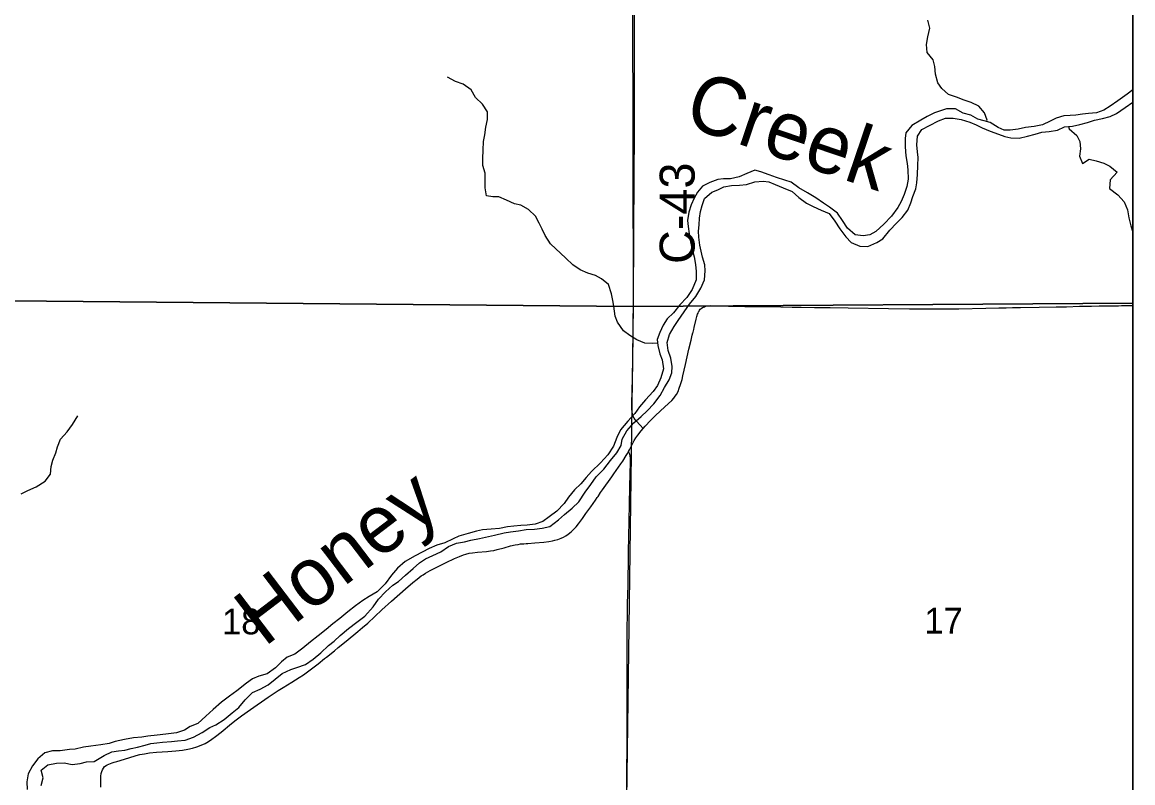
# Model space of a CAD drawing. Extents: x 0 to 34, y 0 to 22.
# Drawn here: x 8.498 to 9.4, y 16.023 to 16.64 of the extents above; entities that cross this region are included whole.
import ezdxf

# ---------------------------------------------------------------- set-up
doc = ezdxf.new("R2010")
doc.units = 0
for name, color, linetype in [('GM_X_County', 7, 'Continuous'), ('GM_X_County_Road', 7, 'Continuous'), ('GM_X_County_Road_Text', 7, 'Continuous'), ('GM_X_Major_River', 7, 'Continuous'), ('GM_X_Major_River_Text', 7, 'Continuous'), ('GM_X_Minor_River', 7, 'Continuous'), ('GM_X_Section', 7, 'Continuous'), ('GM_X_Section_Text', 7, 'Continuous'), ('GM_X_Township', 7, 'Continuous'), ('SH_Data', 7, 'Continuous')]:
    doc.layers.add(name, color=color, linetype=linetype)

msp = doc.modelspace()

# ---------------------------------------------------------------- linework, layer by layer
at = {"layer": 'GM_X_County'}
msp.add_lwpolyline([(9.4, 14.3965), (9.4, 20.9), (2.6, 20.9), (2.6, 14.40919)], dxfattribs=at)
at = {"layer": 'GM_X_County_Road'}
for points in [[(8.99502, 16.63515), (8.99502, 16.64036), (8.99492, 16.65621), (8.99479, 16.66709), (8.99461, 16.68542), (8.99452, 16.69817), (8.99432, 16.71308), (8.9942, 16.72272), (8.99394, 16.73732), (8.99376, 16.75037), (8.9935, 16.77367), (8.99338, 16.78765), (8.99286, 16.83177), (8.99286, 16.85104), (8.99279, 16.86284), (8.99299, 16.89795), (8.99316, 16.91502)], [(8.9947, 16.47621), (8.9947, 16.47732), (8.99482, 16.50653), (8.99498, 16.52734), (8.99508, 16.5376), (8.99515, 16.54752), (8.99518, 16.55526), (8.99515, 16.56581), (8.99511, 16.57793), (8.99505, 16.58942), (8.99506, 16.59377), (8.99506, 16.60153), (8.99504, 16.61488), (8.99502, 16.63515)], [(9.00208, 16.31029), (8.99966, 16.3131), (8.99951, 16.31327), (8.9968, 16.3162), (8.99611, 16.31695), (8.99542, 16.31779), (8.9949, 16.3186), (8.99448, 16.31932), (8.99417, 16.31997), (8.99392, 16.3207), (8.99352, 16.32214), (8.99337, 16.32311), (8.99322, 16.32429), (8.99311, 16.3255), (8.99302, 16.32701), (8.993, 16.3304), (8.99346, 16.35121), (8.99372, 16.36146), (8.99393, 16.37358), (8.99401, 16.37886), (8.99409, 16.38477), (8.99416, 16.39532), (8.99434, 16.4124), (8.99441, 16.42079), (8.99447, 16.42731), (8.99447, 16.43259), (8.99462, 16.44966), (8.9947, 16.47621)], [(9.00208, 16.31029), (9.00377, 16.31219), (9.00827, 16.31691), (9.01204, 16.32061), (9.01636, 16.32464), (9.02279, 16.33051), (9.02542, 16.33314), (9.02706, 16.33502), (9.02826, 16.33661), (9.02921, 16.33804), (9.03052, 16.3405), (9.03156, 16.3431), (9.03256, 16.34604), (9.03376, 16.35022), (9.03452, 16.35323), (9.03665, 16.36231), (9.03942, 16.37475), (9.04111, 16.38201), (9.04212, 16.38624), (9.04256, 16.38805), (9.04275, 16.38864), (9.04326, 16.39076), (9.04367, 16.39226), (9.04532, 16.39921), (9.04587, 16.40132), (9.04642, 16.4031), (9.04682, 16.4041), (9.04722, 16.40495), (9.04758, 16.40565), (9.04807, 16.40648), (9.04863, 16.40716), (9.04938, 16.4079), (9.05029, 16.40852), (9.0511, 16.40892), (9.05194, 16.40927), (9.05284, 16.40957), (9.05465, 16.4099), (9.05682, 16.41009), (9.05934, 16.41006), (9.06276, 16.40996), (9.06525, 16.40996), (9.06773, 16.40987), (9.07146, 16.40977), (9.07643, 16.40968), (9.08482, 16.40947), (9.09507, 16.40936), (9.11403, 16.4091), (9.12335, 16.40898), (9.12584, 16.40894), (9.1305, 16.4089), (9.14137, 16.40873), (9.15411, 16.40854), (9.16872, 16.40837), (9.20164, 16.40788), (9.21871, 16.4076), (9.22679, 16.40754), (9.24046, 16.40741), (9.24916, 16.40743), (9.25879, 16.40758), (9.28054, 16.40811), (9.2911, 16.4083), (9.297, 16.40844), (9.30229, 16.40848), (9.30881, 16.40856), (9.32403, 16.40875), (9.3377, 16.40901), (9.34608, 16.40925), (9.35664, 16.40959), (9.36658, 16.40977), (9.37279, 16.40986), (9.37775, 16.40987), (9.38302, 16.40994), (9.38457, 16.40996), (9.38829, 16.41003), (9.39078, 16.41009), (9.39325, 16.41015), (9.4, 16.41027)], [(8.99035, 16.29169), (8.99096, 16.29288), (8.9937, 16.29844), (8.9949, 16.30062), (8.99621, 16.30274), (8.99779, 16.30504), (9.00046, 16.30847), (9.00208, 16.31029)], [(8.56163, 16.0191), (8.56151, 16.02532), (8.56159, 16.02813), (8.56187, 16.03029), (8.56224, 16.03179), (8.56281, 16.03323), (8.5636, 16.03458), (8.5646, 16.03574), (8.56582, 16.03668), (8.56677, 16.03724), (8.56806, 16.03779), (8.56944, 16.03838), (8.57065, 16.03875), (8.57241, 16.03934), (8.57466, 16.03997), (8.57718, 16.04074), (8.58164, 16.04207), (8.58432, 16.04287), (8.59027, 16.04468), (8.59327, 16.04549), (8.59691, 16.04627), (8.60121, 16.04692), (8.60678, 16.0474), (8.61609, 16.04797), (8.62259, 16.04854), (8.62784, 16.04919), (8.63213, 16.04989), (8.63607, 16.05077), (8.63966, 16.05181), (8.64315, 16.05311), (8.64623, 16.05457), (8.64894, 16.0561), (8.65181, 16.05794), (8.65484, 16.06012), (8.65946, 16.0638), (8.66781, 16.07078), (8.67146, 16.07367), (8.67594, 16.07703), (8.68327, 16.08227), (8.69756, 16.09221), (8.70563, 16.09747), (8.70957, 16.09996), (8.71674, 16.1043), (8.72276, 16.10816), (8.72611, 16.11042), (8.73166, 16.11441), (8.73808, 16.1193), (8.74342, 16.12351), (8.74486, 16.12467), (8.7514, 16.12992), (8.75451, 16.13249), (8.76077, 16.13761), (8.77044, 16.14542), (8.77423, 16.14863), (8.7784, 16.15236), (8.79, 16.16314), (8.79761, 16.17002), (8.80903, 16.1801), (8.81514, 16.18538), (8.81856, 16.18808), (8.82015, 16.18926), (8.82191, 16.19057), (8.82345, 16.19159), (8.82538, 16.19284), (8.82737, 16.19398), (8.82924, 16.195), (8.83336, 16.19718), (8.84227, 16.20161), (8.84902, 16.20478), (8.85302, 16.20649), (8.85621, 16.20771), (8.85804, 16.20835), (8.86082, 16.20904), (8.86345, 16.20945), (8.86746, 16.20991), (8.8749, 16.21051), (8.87829, 16.21095), (8.88074, 16.21137), (8.88346, 16.21198), (8.88917, 16.21354), (8.89428, 16.21495), (8.89816, 16.21585), (8.90053, 16.21627), (8.90262, 16.21655), (8.90337, 16.21658), (8.90382, 16.21668), (8.90447, 16.21671), (8.90532, 16.21681), (8.90703, 16.21694), (8.90841, 16.21704), (8.91413, 16.21749), (8.92155, 16.21815), (8.92556, 16.21865), (8.92862, 16.21919), (8.93043, 16.21961), (8.93282, 16.22028), (8.93546, 16.22122), (8.93743, 16.22213), (8.93932, 16.22321), (8.94139, 16.22458), (8.9436, 16.2263), (8.94566, 16.22819), (8.94779, 16.23045), (8.94975, 16.23286), (8.95303, 16.23738), (8.95571, 16.24119), (8.95958, 16.24682), (8.96335, 16.25215), (8.96477, 16.25418), (8.9655, 16.25519), (8.96753, 16.25828), (8.96917, 16.26054), (8.97673, 16.27118), (8.97836, 16.27345), (8.98408, 16.28159), (8.98563, 16.28391), (8.98849, 16.28833), (8.98956, 16.29016), (8.99035, 16.29169)], [(8.98879, 16.01776), (8.98889, 16.03267), (8.98912, 16.05132), (8.9892, 16.06842), (8.98925, 16.0852), (8.98932, 16.09949), (8.98931, 16.10882), (8.98926, 16.11814), (8.98922, 16.12436), (8.9892, 16.13368), (8.98918, 16.13803), (8.9892, 16.14237), (8.98924, 16.14641), (8.98929, 16.15076), (8.98939, 16.15666), (8.98944, 16.16162), (8.98957, 16.16659), (8.9896, 16.16814), (8.98994, 16.18274), (8.99002, 16.1874), (8.99012, 16.19206), (8.99024, 16.1989), (8.99041, 16.21351), (8.99051, 16.21941), (8.99057, 16.22406), (8.99081, 16.23369), (8.99109, 16.25047), (8.9913, 16.26103), (8.99135, 16.2629), (8.9916, 16.27346), (8.99178, 16.28278), (8.99182, 16.28589), (8.99182, 16.28662), (8.99172, 16.28757), (8.99163, 16.28843), (8.99146, 16.28925), (8.99116, 16.29007), (8.99035, 16.29169)]]:
    msp.add_lwpolyline(points, dxfattribs=at)
at = {"layer": 'GM_X_Major_River'}
for points in [[(9.4, 16.58542), (9.39539, 16.58195), (9.38796, 16.57629), (9.38149, 16.57196), (9.37654, 16.56875), (9.37046, 16.56669), (9.36401, 16.56615), (9.35926, 16.5656), (9.35375, 16.56486), (9.34901, 16.5645)], [(9.34901, 16.5645), (9.34388, 16.56415), (9.3378, 16.56247), (9.33285, 16.55983), (9.32658, 16.55701), (9.31974, 16.55571), (9.31271, 16.55479), (9.30682, 16.55349), (9.30037, 16.55257), (9.29543, 16.55259), (9.29051, 16.55489), (9.28407, 16.5589), (9.27933, 16.56006), (9.27403, 16.5616), (9.26854, 16.56485), (9.26209, 16.56639), (9.25603, 16.56983), (9.24863, 16.56986), (9.24388, 16.56837), (9.23894, 16.56668), (9.23285, 16.56367), (9.2279, 16.56085), (9.22048, 16.55632), (9.21552, 16.55046), (9.21512, 16.54572), (9.21509, 16.53908), (9.21563, 16.53168), (9.21674, 16.52541), (9.21729, 16.52047), (9.21745, 16.51289), (9.21647, 16.50682), (9.21417, 16.50038), (9.21186, 16.49469), (9.20899, 16.48977), (9.20384, 16.48277), (9.19774, 16.47616), (9.19126, 16.4703), (9.18631, 16.46767), (9.181, 16.46674), (9.17436, 16.46753), (9.16831, 16.47306), (9.16416, 16.47934), (9.1602, 16.48524), (9.15358, 16.49001), (9.14866, 16.49344), (9.1426, 16.49765), (9.1356, 16.50166), (9.12859, 16.50586), (9.12235, 16.51044), (9.11723, 16.51198), (9.1106, 16.5141), (9.10453, 16.51621), (9.09771, 16.51871), (9.09297, 16.52025), (9.08632, 16.51743), (9.08023, 16.5148), (9.07302, 16.51312), (9.06751, 16.51296), (9.06276, 16.51241), (9.0563, 16.51016), (9.0504, 16.50715), (9.04621, 16.50223), (9.04353, 16.49731), (9.04123, 16.49201), (9.0393, 16.48594), (9.03833, 16.47931), (9.03887, 16.47437), (9.03961, 16.46829), (9.04034, 16.46336), (9.04184, 16.45671), (9.04351, 16.44987), (9.04463, 16.44361), (9.04517, 16.43772), (9.04514, 16.43108), (9.04207, 16.42312), (9.03768, 16.41669), (9.03196, 16.41083), (9.0268, 16.4044), (9.02166, 16.3993), (9.01841, 16.39438), (9.01573, 16.38832), (9.01361, 16.38264), (9.01416, 16.3777), (9.01565, 16.37087), (9.01753, 16.36612), (9.01864, 16.35871), (9.01652, 16.35151), (9.01383, 16.34526), (9.0104, 16.34034), (9.0041, 16.33354), (8.99915, 16.32786), (8.99533, 16.32257), (8.9898, 16.31633), (8.98388, 16.30914), (8.98082, 16.3029), (8.97813, 16.29589), (8.97336, 16.28908), (8.96744, 16.28246), (8.9602, 16.27547), (8.95601, 16.27055), (8.95143, 16.26545)], [(9.22549, 16.53031), (9.22513, 16.53505), (9.22459, 16.54075), (9.225, 16.54777), (9.22863, 16.55325), (9.23472, 16.55645), (9.24213, 16.56022), (9.24784, 16.56228), (9.2541, 16.56225), (9.26055, 16.56128), (9.26756, 16.55916), (9.27268, 16.55705), (9.2776, 16.55456), (9.28404, 16.55169), (9.29086, 16.54938), (9.29617, 16.54746), (9.30091, 16.5463), (9.30774, 16.54608), (9.31439, 16.54776), (9.32066, 16.54926), (9.32598, 16.55094), (9.33206, 16.55148), (9.3387, 16.55259), (9.34441, 16.55523), (9.35106, 16.55596), (9.35694, 16.55707), (9.36322, 16.55894), (9.36892, 16.56062), (9.37538, 16.56212), (9.38165, 16.5638), (9.38678, 16.56605), (9.39382, 16.57096), (9.4, 16.57537)], [(8.80914, 16.19111), (8.81543, 16.19658), (8.82038, 16.20131), (8.82533, 16.20451), (8.83142, 16.20733), (8.83769, 16.21015), (8.84398, 16.21449), (8.85063, 16.21712), (8.8569, 16.21823), (8.86222, 16.21972), (8.86925, 16.22102), (8.87646, 16.22251), (8.8814, 16.22363), (8.88919, 16.22549), (8.89451, 16.22641), (8.90078, 16.22734), (8.90705, 16.22845), (8.91388, 16.22861), (8.92015, 16.22934), (8.92623, 16.23083), (8.93346, 16.23612), (8.93823, 16.24046), (8.94451, 16.24574), (8.95004, 16.25085), (8.9552, 16.2586), (8.95978, 16.26485), (8.96398, 16.27109), (8.97027, 16.27732), (8.97561, 16.28432), (8.98076, 16.29056), (8.98421, 16.29662), (8.98518, 16.30155), (8.989, 16.30836), (8.99454, 16.31498), (9.00044, 16.32008), (9.00539, 16.32461), (9.01092, 16.33047), (9.01589, 16.33709), (9.01952, 16.34353), (9.02334, 16.34996), (9.02546, 16.35564), (9.02567, 16.36058), (9.02456, 16.36741), (9.0225, 16.37368), (9.02177, 16.38014), (9.02369, 16.38658), (9.02733, 16.39321), (9.03057, 16.39813), (9.03554, 16.40513), (9.03974, 16.41118), (9.04508, 16.41761), (9.0491, 16.42423), (9.05197, 16.43105), (9.05257, 16.43845), (9.0524, 16.44319), (9.05034, 16.44946), (9.04923, 16.45421), (9.04811, 16.45915), (9.04738, 16.46579), (9.04702, 16.47054), (9.04761, 16.47566), (9.04801, 16.48116), (9.0488, 16.48647), (9.05015, 16.4914), (9.05207, 16.49708), (9.05797, 16.50218), (9.06273, 16.50425), (9.06786, 16.5065), (9.07394, 16.5078), (9.08058, 16.50797), (9.08609, 16.50851), (9.09293, 16.51076), (9.09958, 16.51111), (9.10432, 16.51052), (9.10943, 16.50841), (9.11588, 16.50573), (9.12327, 16.50285), (9.12856, 16.49789), (9.1348, 16.49331), (9.14029, 16.49063), (9.14673, 16.48776), (9.15336, 16.48489), (9.15789, 16.4788), (9.16185, 16.47252), (9.16695, 16.46604), (9.17129, 16.46128), (9.17811, 16.45841), (9.18475, 16.458), (9.19198, 16.46138), (9.19693, 16.4644), (9.20265, 16.47139), (9.20799, 16.47706), (9.21276, 16.48179), (9.21734, 16.48765), (9.21964, 16.49371), (9.22118, 16.49864), (9.22368, 16.50508), (9.22464, 16.50982), (9.22505, 16.51665), (9.22546, 16.52386), (9.22549, 16.53031)], [(8.95143, 16.26545), (8.94647, 16.26054), (8.94151, 16.25449), (8.93807, 16.24938), (8.93197, 16.24314), (8.92569, 16.23862), (8.92055, 16.23484), (8.91447, 16.23259), (8.90782, 16.23186), (8.90289, 16.23169), (8.897, 16.23115), (8.89206, 16.23041), (8.8856, 16.22911), (8.87877, 16.22857), (8.87174, 16.22803), (8.86681, 16.2271), (8.85996, 16.22505), (8.85255, 16.2228), (8.8478, 16.22073), (8.84095, 16.21754), (8.83468, 16.21548), (8.82841, 16.21285), (8.8227, 16.20984), (8.81699, 16.20701), (8.80881, 16.20231), (8.80271, 16.19683), (8.79776, 16.19116), (8.7926, 16.18416), (8.78612, 16.17773), (8.77946, 16.17397), (8.77432, 16.17076), (8.76842, 16.16642), (8.76233, 16.16152), (8.75585, 16.15604), (8.74995, 16.1517), (8.74461, 16.14717), (8.73814, 16.14189), (8.73185, 16.13717), (8.72576, 16.13207), (8.71929, 16.12717), (8.71301, 16.12473), (8.70825, 16.12076), (8.70348, 16.11604), (8.69663, 16.11114), (8.68998, 16.10927), (8.68466, 16.10701), (8.6799, 16.10362), (8.67209, 16.0972), (8.666, 16.09305), (8.65952, 16.08815), (8.65285, 16.0821), (8.64676, 16.07663), (8.64028, 16.07077), (8.63419, 16.06833), (8.62944, 16.0655), (8.62297, 16.06326), (8.61443, 16.06215), (8.6074, 16.06123), (8.59981, 16.06051), (8.59487, 16.05977), (8.58803, 16.05923), (8.58082, 16.05774), (8.57322, 16.05626), (8.56846, 16.05457), (8.56144, 16.05346), (8.55346, 16.05236), (8.54757, 16.05144), (8.54073, 16.04995), (8.53599, 16.04959), (8.52858, 16.04867), (8.52232, 16.0487), (8.51605, 16.04702), (8.51033, 16.04211), (8.50594, 16.03644), (8.5025, 16.02981), (8.50152, 16.02336), (8.50169, 16.0171)], [(8.51309, 16.02047), (8.51463, 16.02653), (8.51295, 16.0328), (8.51847, 16.03714), (8.5255, 16.03863), (8.53177, 16.03879), (8.53821, 16.03743), (8.54486, 16.03835), (8.54999, 16.03966), (8.55625, 16.04001), (8.56425, 16.04491), (8.57052, 16.04773), (8.57603, 16.04847), (8.58116, 16.0492), (8.58629, 16.05051), (8.59142, 16.05163), (8.5975, 16.05331), (8.60225, 16.05462), (8.607, 16.05517), (8.61174, 16.05552), (8.61896, 16.05625), (8.62389, 16.0568), (8.63016, 16.05734), (8.63681, 16.05959), (8.64385, 16.06354), (8.65013, 16.0675), (8.65489, 16.06976), (8.66174, 16.0739), (8.6684, 16.07938), (8.67374, 16.08372), (8.6787, 16.08996), (8.6848, 16.09582), (8.69107, 16.09864), (8.69754, 16.10221), (8.70897, 16.11127), (8.71601, 16.11466), (8.72076, 16.11635), (8.72798, 16.11878), (8.73407, 16.12293), (8.74036, 16.12822), (8.74646, 16.13407), (8.75122, 16.13766), (8.75598, 16.14219), (8.76265, 16.14804), (8.7695, 16.15314), (8.77598, 16.15804), (8.78284, 16.16541), (8.78723, 16.17185), (8.79276, 16.17771), (8.79867, 16.18299), (8.80343, 16.1862), (8.80914, 16.19111)]]:
    msp.add_lwpolyline(points, dxfattribs=at)
at = {"layer": 'GM_X_Minor_River'}
for points in [[(9.28127, 16.55958), (9.28161, 16.56081), (9.27955, 16.5667), (9.27502, 16.57222), (9.26877, 16.57509), (9.26289, 16.57701), (9.25683, 16.57951), (9.2502, 16.58143), (9.2449, 16.58639), (9.24151, 16.59115), (9.23983, 16.59798), (9.2391, 16.60425), (9.23779, 16.60976), (9.23289, 16.61566), (9.23253, 16.62211), (9.23351, 16.62837), (9.23506, 16.63538), (9.23357, 16.64184)], [(9.01395, 16.37967), (9.0098, 16.37924), (9.00354, 16.37965), (8.9971, 16.38233), (8.99123, 16.38577), (8.98632, 16.38978), (8.98122, 16.39682), (8.97953, 16.40157), (8.97824, 16.40955), (8.9775, 16.41429), (8.97657, 16.41961), (8.97414, 16.42721), (8.96828, 16.43198), (8.96335, 16.43447), (8.95729, 16.43639), (8.95104, 16.43926), (8.94517, 16.44327), (8.93931, 16.44861), (8.92684, 16.46043), (8.92269, 16.46709), (8.92005, 16.47222), (8.91761, 16.47697), (8.91478, 16.48268), (8.90911, 16.48821), (8.90268, 16.49165), (8.89775, 16.49281), (8.89112, 16.49587), (8.88505, 16.49837), (8.87993, 16.49858), (8.87481, 16.49936), (8.8737, 16.50581), (8.87391, 16.51113), (8.87375, 16.51758), (8.87188, 16.52404), (8.8719, 16.52954), (8.87212, 16.53637), (8.87253, 16.54339), (8.87351, 16.54889), (8.87448, 16.55514), (8.87584, 16.56121), (8.87567, 16.56747), (8.87153, 16.57375), (8.86586, 16.57909), (8.86247, 16.58536), (8.85603, 16.58994), (8.84959, 16.59206), (8.84334, 16.59569)], [(9.3478, 16.5556), (9.3482, 16.55369), (9.35444, 16.54835), (9.35707, 16.54341), (9.35762, 16.53752), (9.35683, 16.53146), (9.35908, 16.52556), (9.3646, 16.52896), (9.37029, 16.52779), (9.37655, 16.52587), (9.38147, 16.52338), (9.38733, 16.51842), (9.38161, 16.51219), (9.3812, 16.50517), (9.38782, 16.50021), (9.39311, 16.49449), (9.39574, 16.48784), (9.39685, 16.48138), (9.39853, 16.47492), (9.4, 16.46977)], [(8.49683, 16.25716), (8.50216, 16.25998), (8.509, 16.26299), (8.51623, 16.2677), (8.52062, 16.27318), (8.52122, 16.27944), (8.52257, 16.28456), (8.52506, 16.29062), (8.52622, 16.29536), (8.52891, 16.30161), (8.53425, 16.30766), (8.53864, 16.31352), (8.54284, 16.32053)]]:
    msp.add_lwpolyline(points, dxfattribs=at)
at = {"layer": 'GM_X_Section'}
for p, q in [((9.4, 16.41212), (9.4, 16.90956)), ((9.4, 15.90931), (9.4, 16.41212))]:
    msp.add_line(p, q, dxfattribs=at)
for points in [[(8.48909, 16.91461), (8.9931, 16.91603), (8.99394, 16.40937), (8.48751, 16.41403)], [(8.48751, 16.41403), (8.99394, 16.40937), (8.98723, 15.90883), (8.47945, 15.90819), (8.48728, 16.40835)]]:
    msp.add_lwpolyline(points, close=True, dxfattribs=at)
for points in [[(9.4, 16.90956), (8.9931, 16.91603), (8.99394, 16.40937), (9.4, 16.41212)], [(9.4, 16.41212), (8.99394, 16.40937), (8.98723, 15.90883), (9.4, 15.90931)]]:
    msp.add_lwpolyline(points, dxfattribs=at)
at = {"layer": 'GM_X_Township'}
msp.add_line((9.4, 14.3965), (9.4, 17.40915), dxfattribs=at)
at = {"layer": 'SH_Data'}
msp.add_line((9.4, 20.9), (9.4, 14.1), dxfattribs=at)

# ---------------------------------------------------------------- texts
at = {"layer": 'GM_X_County_Road_Text'}
msp.add_text('C-43', height=0.028409, rotation=90, dxfattribs=at).set_placement((9.04401, 16.44397))
at = {"layer": 'GM_X_Major_River_Text'}
for s, height, rotation, p in [('Creek', 0.047366, 341.27206, (9.03358, 16.557)), ('Honey', 0.047368, 37.30059, (8.69425, 16.13234))]:
    msp.add_text(s, height=height, rotation=rotation, dxfattribs=at).set_placement(p)
at = {"layer": 'GM_X_Section_Text'}
for s, p in [('18', (8.66007, 16.14317)), ('17', (9.23069, 16.14384))]:
    msp.add_text(s, height=0.020928, rotation=0.00001, dxfattribs=at).set_placement(p)

doc.saveas('drawing.dxf')
